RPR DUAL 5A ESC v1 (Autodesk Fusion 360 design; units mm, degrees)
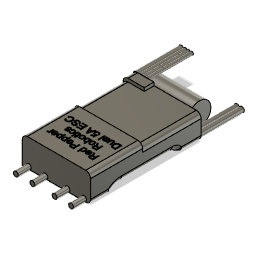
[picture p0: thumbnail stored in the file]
sketch "Sketch1" plane through (0, 0, 0) normal (0, 1, 0) x axis (1, 0, 0)
  line L1 (-10.5, -17) -> (10.5, -17)
  line L2 (-10.5, 17) -> (-10.5, -17)
  line L3 (10.5, 17) -> (-10.5, 17)
  line L4 (10.5, -17) -> (10.5, 17)
  line L5 (-10.5, 17) -> (10.5, -17)
  line L6 (10.5, 17) -> (-10.5, -17)
  point P6 (0, 0)
  point P1 (0, 0)
  point P4 (-10.5, 17)
  point P5 (10.5, 17)
  point P3 (-10.5, -17)
  horizontal L1
  perpendicular L1 L2
  parallel L1 L3
  parallel L2 L4
  coincident L5 P6
  coincident L6 P6
  coincident P1 P6
  dimension "d1" distance P4 P5 = 21
  dimension "d2" distance P3 P4 = 34
extrude "Extrude1" new body sketch "Sketch1" + "Sketch5" profile of S1:L1 S1:L2 S1:L3 S1:L4 blind 8.5
sketch "Sketch2" plane through (10.5, 0, 0) normal (1, 0, 0) x axis (0, 0, -1)
  line L1 (17, 0) -> (-17, 0)
  line L2 (17, 8.5) -> (17, 0)
  line L3 (-17, 8.5) -> (17, 8.5)
  line L4 (-17, 0) -> (-17, 8.5)
  circle C1 centre (21.25, 4.25) radius 4.25
  point P6 (21.25, 4.25)
  dimension "d5" diameter C1 = 8.5
  dimension "d6" distance L2 P6 = 4.25
  dimension "d7" distance L1 P6 = 4.25
extrude "Extrude2" new body sketch "Sketch2" + "Sketch5" profile of S1:C1 blind -21
sketch "Sketch3" plane through (10.5, 0, 0) normal (1, 0, 0) x axis (0, 0, -1)
  line L1 (17, 0) -> (-17, 0)
  line L2 (17, 8.5) -> (17, 0)
  line L3 (-17, 8.5) -> (17, 8.5)
  line L4 (-17, 0) -> (-17, 8.5)
  line L5 (-1, 8.5) -> (17, 8.5)
  line L6 (-1, 7.5) -> (-1, 8.5)
  line L7 (17, 7.5) -> (-1, 7.5)
  line L8 (17, 8.5) -> (17, 7.5)
  point P4 (17, 8.5)
  point P6 (17, 8.5)
  point P7 (-1, 8.5)
  point P9 (17, 7.5)
  horizontal L5
  vertical L6
  horizontal L7
  vertical L8
  coincident P4 P6
  dimension "d10" distance P6 P7 = 18
  dimension "d11" distance P6 P9 = 1
extrude "Extrude3" cut sketch "Sketch3" profile of L2 L3 L5 L6 L7 L8 against normal blind 21
sketch "Sketch4" plane through (-10.5, 0, 0) normal (-1, 0, 0) x axis (0, 0, 1)
  line L1 (-17, 7.5) -> (1, 7.5)
  line L2 (-17, 0) -> (-17, 7.5)
  line L3 (17, 0) -> (-17, 0)
  line L4 (17, 8.5) -> (17, 0)
  line L5 (1, 8.5) -> (17, 8.5)
  line L6 (1, 7.5) -> (1, 8.5)
  line L7 (17, 1.5) -> (-17, 1.5)
  line L8 (17, 0) -> (17, 1.5)
  line L9 (-17, 0) -> (17, 0)
  line L10 (-17, 1.5) -> (-17, 0)
  point P5 (17, 0)
  point P10 (17, 0)
  point P8 (-17, 1.5)
  horizontal L7
  vertical L8
  horizontal L9
  vertical L10
  coincident P5 P10
  coincident L2 P8
  dimension "d14" distance L7 L9 = 1.5
extrude "Extrude4" cut sketch "Sketch4" profile of L2 L3 L4 L7 L8 L9 L10 against normal blind 21
extrude "Extrude5" cut of existing geometry blind -4
sketch "Sketch5" plane through (0, 1.5, 0) normal (0, -1, 0) x axis (1, 0, 0)
  line L1 (-10.5, -17) -> (-10.5, 17)
  line L2 (10.5, -17) -> (-10.5, -17)
  line L3 (10.5, 17) -> (10.5, -17)
  line L4 (-10.5, 17) -> (10.5, 17)
  line L5 (5, -17) -> (10.5, -17)
  line L6 (5, -10) -> (5, -17)
  line L7 (10.5, -10) -> (5, -10)
  line L8 (10.5, -17) -> (10.5, -10)
  point P4 (10.5, -17)
  point P6 (10.5, -17)
  horizontal L5
  vertical L6
  horizontal L7
  vertical L8
  coincident P4 P6
extrude "Extrude6" add sketch "Sketch5" profile of L2 L3 L5 L6 L7 L8 along normal blind 1.5
fillet "Fillet1" radius 2
sketch "Sketch6" plane through (0, 0, -17) normal (0, 0, -1) x axis (-1, 0, 0)
  line L1 (10.5, 1.5) -> (-3.0635, 1.5)
  line L2 (10.5, 7.5) -> (10.5, 1.5)
  line L3 (-10.5, 7.5) -> (10.5, 7.5)
  line L4 (-10.5, 0) -> (-10.5, 7.5)
  line L5 (-5, 0) -> (-10.5, 0)
  arc A1 centre (-3.0635, -0.5) radius 2 clockwise from (-5, 0) to (-3.0635, 1.5)
  circle C1 centre (-9.0288, 0.75) radius 0.75
  circle C2 centre (-7.5288, 0.75) radius 0.75
  tangent C1 C2
  tangent L5 C1
  tangent L5 C2
  dimension "d23" diameter C1 = 1.5
  dimension "d24" diameter C2 = 1.5
extrude "Extrude7" new body sketch "Sketch6" + "Sketch5" profile of S1:C1 S1:C2 blind 14
fillet "Fillet2" radius 1.5
sketch "Sketch7" plane through (0, 1.5, 0) normal (0, -1, 0) x axis (1, 0, 0)
  line L1 (10.5, -8.0635) -> (3.0635, -8.0635)
  line L2 (10.5, 17) -> (10.5, -8.0635)
  line L3 (-10.5, 17) -> (10.5, 17)
  line L4 (-10.5, -17) -> (-10.5, 17)
  line L5 (3.0635, -17) -> (-10.5, -17)
  line L6 (3.0635, -8.0635) -> (3.0635, -17)
  line L7 (-10.5, 17) -> (10.5, 17)
  line L8 (-10.5, 11) -> (-10.5, 17)
  line L9 (10.5, 11) -> (-10.5, 11)
  line L10 (10.5, 17) -> (10.5, 11)
  point P4 (10.5, 17)
  point P8 (10.5, 17)
  point P11 (10.5, 11)
  horizontal L7
  vertical L8
  horizontal L9
  vertical L10
  coincident P4 P8
  dimension "d29" distance P8 P11 = 6
extrude "Extrude8" add sketch "Sketch7" profile of L2 L3 L4 L7 L8 L9 L10 along normal blind 1.5
fillet "Fillet3" radius 5
sketch "Sketch8" plane through (0, 0, 17) normal (0, 0, 1) x axis (1, 0, 0)
  line L1 (10.5, 8.5) -> (10.5, 0)
  line L2 (-10.5, 8.5) -> (10.5, 8.5)
  line L3 (-10.5, 0) -> (-10.5, 8.5)
  line L4 (10.5, 0) -> (-10.5, 0)
  circle C1 centre (-8.5, 0.75) radius 0.75
  circle C2 centre (-3.4, 0.75) radius 0.75
  circle C3 centre (3.4, 0.75) radius 0.75
  circle C4 centre (8.5, 0.75) radius 0.75
  point P6 (-8.5, 0.75)
  point P9 (8.5, 0.75)
  point P8 (3.4, 0.75)
  point P7 (-3.4, 0.75)
  tangent L4 C4
  tangent L4 C3
  tangent L4 C2
  tangent L4 C1
  dimension "d34" diameter C1 = 1.5
  dimension "d35" diameter C2 = 1.5
  dimension "d36" diameter C3 = 1.5
  dimension "d37" diameter C4 = 1.5
  dimension "d38" distance L3 P6 = 2
  dimension "d39" distance L1 P9 = 2
  dimension "d40" distance P8 P9 = 5.1
  dimension "d41" distance P6 P7 = 5.1
extrude "Extrude9" add sketch "Sketch8" profile of C1 C2 C3 C4 along normal blind 4
sketch "Sketch9" plane through (0, 7.5, 0) normal (0, 1, 0) x axis (-1, 0, 0)
  line L1 (-10.5, -17) -> (-10.5, 1)
  line L2 (10.5, -17) -> (-10.5, -17)
  line L3 (10.5, 1) -> (10.5, -17)
  line L4 (-10.5, 1) -> (10.5, 1)
  line L5 (4, -17) -> (10.5, -17)
  line L6 (4, -14) -> (4, -17)
  line L7 (10.5, -14) -> (4, -14)
  line L8 (10.5, -17) -> (10.5, -14)
  point P4 (10.5, -17)
  point P6 (10.5, -17)
  horizontal L5
  vertical L6
  horizontal L7
  vertical L8
  coincident P4 P6
extrude "Extrude10" add sketch "Sketch9" profile of L2 L3 L5 L6 L7 L8 along normal blind 1
sketch "Sketch10" plane through (0, 0, -17) normal (0, 0, -1) x axis (-1, 0, 0)
  line L1 (-5, 0) -> (-9, 0)
  line L2 (10.5, 1.5) -> (-3.0635, 1.5)
  line L3 (10.5, 8.5) -> (10.5, 1.5)
  line L4 (4, 8.5) -> (10.5, 8.5)
  line L5 (4, 7.5) -> (4, 8.5)
  line L6 (-10.5, 7.5) -> (4, 7.5)
  line L7 (-10.5, 1.5) -> (-10.5, 7.5)
  arc A1 centre (-9, 1.5) radius 1.5 clockwise from (-9, 0) to (-10.5, 1.5)
  arc A2 centre (-3.0635, -0.5) radius 2 clockwise from (-5, 0) to (-3.0635, 1.5)
  circle C1 centre (9.6, 7.75) radius 0.75
  circle C2 centre (8.3753, 8) radius 0.5
  circle C3 centre (7.3753, 8) radius 0.5
  circle C4 centre (6.3753, 8) radius 0.5
  tangent L4 C4
  tangent L4 C3
  tangent L4 C2
  tangent C2 C3
  tangent C3 C4
  tangent C1 C2
  tangent L4 C1
  dimension "d46" diameter C1 = 1.5
  dimension "d47" diameter C2 = 1
  dimension "d48" diameter C3 = 1
  dimension "d49" diameter C4 = 1
extrude "Extrude11" new body sketch "Sketch10" + "Sketch5" profile of S1:C1 S1:C2 S1:C3 S1:C4 blind 14
sketch "Sketch11" plane through (-10.5, 0, 0) normal (-1, 0, 0) x axis (0, 0, 1)
  line L1 (-17, 8.5) -> (-17, 1.5)
  line L2 (-17, 0) -> (-10, 0)
  circle C1 centre (-21.25, 4.25) radius 4.25
  circle C2 centre (-20.5, 3.5) radius 3.5
  tangent C2 L1
  tangent C2 L2
  dimension "d52" diameter C2 = 7
extrude "Extrude12" cut sketch "Sketch11" profile of C1 C2 against normal blind 17
extrude "Extrude13" add sketch "Sketch11" profile of C1 C2 against normal blind 17
extrude "Extrude14" cut of existing geometry blind -2
fillet "Fillet4" radius 1.5
sketch "Sketch12" plane through (0, 8.5, 0) normal (0, 1, 0) x axis (-1, 0, 0)
  dimension "d61" = 2
extrude "Extrude15" cut sketch "Sketch12" against normal blind 0.25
